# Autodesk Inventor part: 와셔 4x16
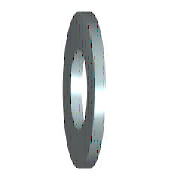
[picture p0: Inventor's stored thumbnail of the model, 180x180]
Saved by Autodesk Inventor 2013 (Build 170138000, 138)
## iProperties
IsCustomPart: 1
Created: 2012-02
Part Number: 와셔 4x16
Material: 강철, 연강
Description: 미터법 평면 와셔
Document SubType Name: Modeling
Standard: ANSI B18.22M
Designer: mduedu
Standard Revision: 1999
Standards Organization: ANSI
Language: ko-KR
Size Designation: 4 W
Categories: <MemberInstance><Categories><Category DisplayName="조임쇠" InternalName="e4da775c-781d-43d5-af7c-5136215cf5a6" Mnemonic="FSTN"><Category DisplayName="와셔" InternalN
Density: 7.86 g/cm^3
Mass: 3.32115 g
Surface Area: 5.16996 cm^2
Volume: 0.422539 cm^3
Author: mduedu
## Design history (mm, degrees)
sketch "스케치"
  geometry: C1 r 8 at (0, 0); C2 r 2.35 at (0, 0); 1 further point
  constraints: 2 centre point, 2 coincident
  dimensions: "d0" = 4.7 diameter of C2 (= SD1); "d1" = 16 diameter of C1 (= SD2)
extrude "본체" new body sketch "스케치" distance "d2" = 2.3 (= SD); taper "d3" = 0 deg
workaxis "Work Axis1"
workplane "Work Plane1"
body "Solid1"
other parameters: "SD1" = 4.7 [user parameter; used in 1 equation term], "SD2" = 16 [user parameter; used in 1 equation term], "SD" = 2.3 [user parameter; used in 1 equation term], "d4" = 0, "d5" = 0, "d6" = 0, "d7" = 0, "NND" = 4 [user parameter]
